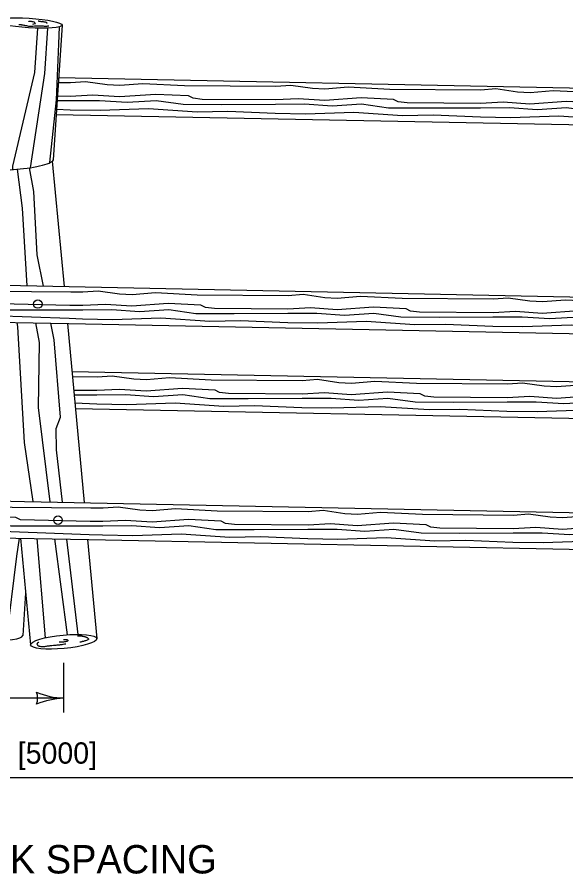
# Model space of a CAD drawing. Extents: x 49991.4 to 50021, y 49987.6 to 50011.4.
# Drawn here: x 50012.107 to 50013.653, y 49994.539 to 49996.952 of the extents above; entities that cross this region are included whole.
import ezdxf

# ---------------------------------------------------------------- set-up
doc = ezdxf.new("R2010")
doc.units = 0
for name, color, linetype in [('Level 1', 7, 'Continuous'), ('Level 2', 7, 'Continuous'), ('Level 3', 7, 'Continuous')]:
    doc.layers.add(name, color=color, linetype=linetype)

msp = doc.modelspace()

# ---------------------------------------------------------------- linework, layer by layer
at = {"layer": 'Level 1'}
for p, q in [((50012.2339, 49996.9293), (50012.2091, 49996.5495)), ((50012.2243, 49996.7817), (50014.3417, 49996.7388)), ((50012.2175, 49996.6777), (50014.3351, 49996.6363)), ((50012.2063, 49996.5461), (50012.2392, 49996.193)), ((50012.0713, 49996.1964), (50014.3767, 49996.1497)), ((50009.7813, 49996.137), (50012.2525, 49996.0886)), ((50012.2489, 49996.0887), (50012.2959, 49995.5846)), ((50012.2525, 49996.0886), (50014.3701, 49996.0471)), ((50012.2615, 49995.9539), (50014.2538, 49995.9136)), ((50012.2712, 49995.8496), (50014.2819, 49995.8102)), ((50009.8457, 49995.6343), (50012.128, 49995.588)), ((50012.128, 49995.588), (50014.4334, 49995.5413)), ((50009.838, 49995.5286), (50012.3092, 49995.4802)), ((50012.1166, 49995.484), (50012.1446, 49995.1842)), ((50012.3056, 49995.4803), (50012.3315, 49995.2015)), ((50012.3092, 49995.4802), (50014.4268, 49995.4387)), ((50012.1309, 49995.3305), (50012.1232, 49995.2101))]:
    msp.add_line(p, q, dxfattribs=at)
for points in [[(50012.095, 49996.5216), (50012.0953, 49996.5317), (50012.157, 49996.7957), (50012.1651, 49996.9206)], [(50012.1449, 49996.5276), (50012.1855, 49996.7929), (50012.1938, 49996.9208)], [(50012.1996, 49996.5421), (50012.2176, 49996.7186), (50012.2244, 49996.8769), (50012.2262, 49996.9246)], [(50012.2577, 49996.7663), (50012.2233, 49996.7666)], [(50012.8356, 49996.7562), (50012.5791, 49996.7583), (50012.4615, 49996.7642), (50012.3962, 49996.7589), (50012.3609, 49996.7608), (50012.3, 49996.7696), (50012.2577, 49996.7663)], [(50013.4136, 49996.7461), (50013.157, 49996.7482), (50013.0395, 49996.7541), (50012.9742, 49996.7488), (50012.9388, 49996.7507), (50012.878, 49996.7595), (50012.8356, 49996.7562)], [(50013.9915, 49996.736), (50013.7349, 49996.7381), (50013.6174, 49996.744), (50013.5521, 49996.7387), (50013.5167, 49996.7406), (50013.4559, 49996.7494), (50013.4135, 49996.7461)], [(50012.2568, 49996.7159), (50012.22, 49996.7157)], [(50012.257, 49996.7286), (50012.2208, 49996.7289)], [(50012.8347, 49996.7058), (50012.6831, 49996.7051), (50012.5753, 49996.7057), (50012.4991, 49996.7162), (50012.4167, 49996.711), (50012.3388, 49996.7162), (50012.2568, 49996.7159)], [(50012.835, 49996.7185), (50012.628, 49996.7201), (50012.6026, 49996.7232), (50012.5899, 49996.7298), (50012.498, 49996.7341), (50012.3957, 49996.7268), (50012.3207, 49996.7319), (50012.257, 49996.7286)], [(50013.4129, 49996.7085), (50013.2059, 49996.7101), (50013.1805, 49996.7131), (50013.1678, 49996.7197), (50013.0759, 49996.724), (50012.9736, 49996.7167), (50012.8986, 49996.7219), (50012.8349, 49996.7185)], [(50012.2564, 49996.6901), (50012.2184, 49996.6917)], [(50012.8343, 49996.68), (50012.7011, 49996.6855), (50012.6146, 49996.6839), (50012.4773, 49996.6932), (50012.3411, 49996.6886), (50012.2564, 49996.6901)], [(50013.4127, 49996.6957), (50013.261, 49996.695), (50013.1533, 49996.6956), (50013.077, 49996.7061), (50012.9946, 49996.7009), (50012.9167, 49996.7061), (50012.8347, 49996.7058)], [(50013.9906, 49996.6857), (50013.8389, 49996.6849), (50013.7312, 49996.6855), (50013.6549, 49996.6961), (50013.5725, 49996.6908), (50013.4946, 49996.6961), (50013.4127, 49996.6957)], [(50013.9908, 49996.6984), (50013.7839, 49996.7), (50013.7584, 49996.703), (50013.7458, 49996.7097), (50013.6539, 49996.7139), (50013.5515, 49996.7066), (50013.4765, 49996.7118), (50013.4129, 49996.7085)], [(50013.4122, 49996.67), (50013.279, 49996.6754), (50013.1925, 49996.6738), (50013.0553, 49996.6832), (50012.9191, 49996.6786), (50012.8343, 49996.68)], [(50013.9901, 49996.6599), (50013.857, 49996.6654), (50013.7705, 49996.6637), (50013.6332, 49996.6731), (50013.497, 49996.6685), (50013.4122, 49996.67)], [(50012.135, 49996.1951), (50012.1222, 49996.4133), (50012.1078, 49996.5231)], [(50012.1816, 49996.1942), (50012.164, 49996.2823), (50012.1538, 49996.4607), (50012.1419, 49996.5271)], [(50012.2583, 49996.1774), (50012.0362, 49996.1792), (50011.9186, 49996.1851), (50011.8534, 49996.1798), (50011.818, 49996.1817), (50011.7572, 49996.1905), (50011.7148, 49996.1872)], [(50012.2927, 49996.1771), (50012.2583, 49996.1774)], [(50012.8707, 49996.1671), (50012.6141, 49996.1691), (50012.4966, 49996.175), (50012.4313, 49996.1697), (50012.3959, 49996.1716), (50012.3351, 49996.1804), (50012.2927, 49996.1771)], [(50013.4486, 49996.157), (50013.192, 49996.1591), (50013.0745, 49996.165), (50013.0092, 49996.1597), (50012.9738, 49996.1616), (50012.913, 49996.1704), (50012.8706, 49996.1671)], [(50014.0265, 49996.1469), (50013.7699, 49996.149), (50013.6524, 49996.1549), (50013.5871, 49996.1496), (50013.5517, 49996.1515), (50013.4909, 49996.1603), (50013.4485, 49996.157)], [(50012.2559, 49996.1398), (50012.0597, 49996.1441), (50012.047, 49996.1508), (50011.9551, 49996.155), (50011.8528, 49996.1477), (50011.7778, 49996.1529), (50011.7141, 49996.1496)], [(50012.2921, 49996.1395), (50012.2559, 49996.1398)], [(50012.87, 49996.1294), (50012.663, 49996.131), (50012.6376, 49996.1341), (50012.625, 49996.1407), (50012.533, 49996.1449), (50012.4307, 49996.1377), (50012.3557, 49996.1428), (50012.292, 49996.1395)], [(50012.2534, 49996.1025), (50011.9344, 49996.1142), (50011.7982, 49996.1096), (50011.7135, 49996.1111)], [(50012.2918, 49996.1268), (50012.0668, 49996.1264)], [(50012.8698, 49996.1167), (50012.7181, 49996.1159), (50012.6104, 49996.1165), (50012.5341, 49996.1271), (50012.4517, 49996.1219), (50012.3738, 49996.1271), (50012.2918, 49996.1268)], [(50013.4477, 49996.1066), (50013.296, 49996.1059), (50013.1883, 49996.1065), (50013.112, 49996.117), (50013.0296, 49996.1118), (50012.9517, 49996.117), (50012.8698, 49996.1167)], [(50013.4479, 49996.1193), (50013.241, 49996.1209), (50013.2155, 49996.124), (50013.2029, 49996.1306), (50013.111, 49996.1349), (50013.0086, 49996.1276), (50012.9336, 49996.1327), (50012.87, 49996.1294)], [(50014.0258, 49996.1093), (50013.8189, 49996.1109), (50013.7934, 49996.1139), (50013.7808, 49996.1206), (50013.6889, 49996.1248), (50013.5866, 49996.1175), (50013.5115, 49996.1227), (50013.4479, 49996.1193)], [(50012.1522, 49995.5875), (50012.128, 49995.7534), (50012.1093, 49996.0799), (50012.1074, 49996.0915)], [(50012.1999, 49995.5865), (50012.1677, 49995.8525), (50012.1699, 49996.0355), (50012.1594, 49996.0904)], [(50012.235, 49995.5858), (50012.2176, 49995.7327), (50012.2171, 49995.7936), (50012.229, 49995.8253), (50012.2116, 49996.0433), (50012.2024, 49996.0896)], [(50012.2914, 49996.101), (50012.2534, 49996.1025)], [(50012.8693, 49996.0909), (50012.7361, 49996.0964), (50012.6496, 49996.0947), (50012.5124, 49996.1041), (50012.3762, 49996.0995), (50012.2914, 49996.101)], [(50013.4472, 49996.0808), (50013.3141, 49996.0863), (50013.2276, 49996.0847), (50013.0903, 49996.0941), (50012.9541, 49996.0894), (50012.8693, 49996.0909)], [(50014.0256, 49996.0966), (50013.8739, 49996.0958), (50013.7662, 49996.0964), (50013.6899, 49996.107), (50013.6076, 49996.1017), (50013.5297, 49996.107), (50013.4477, 49996.1066)], [(50014.0252, 49996.0708), (50013.892, 49996.0762), (50013.8055, 49996.0746), (50013.6682, 49996.084), (50013.532, 49996.0794), (50013.4472, 49996.0808)], [(50012.3326, 49995.9377), (50012.2629, 49995.9383)], [(50012.9106, 49995.9277), (50012.654, 49995.9297), (50012.5365, 49995.9356), (50012.4712, 49995.9303), (50012.4358, 49995.9322), (50012.375, 49995.941), (50012.3326, 49995.9377)], [(50013.4885, 49995.9176), (50013.2319, 49995.9197), (50013.1144, 49995.9256), (50013.0491, 49995.9203), (50013.0137, 49995.9222), (50012.9529, 49995.931), (50012.9105, 49995.9277)], [(50014.0664, 49995.9075), (50013.8098, 49995.9096), (50013.6923, 49995.9155), (50013.627, 49995.9102), (50013.5916, 49995.9121), (50013.5308, 49995.9209), (50013.4884, 49995.9176)], [(50012.332, 49995.9001), (50012.2665, 49995.9006)], [(50012.9099, 49995.89), (50012.703, 49995.8916), (50012.6775, 49995.8946), (50012.6649, 49995.9013), (50012.5729, 49995.9055), (50012.4706, 49995.8983), (50012.3956, 49995.9034), (50012.3319, 49995.9001)], [(50013.4878, 49995.8799), (50013.2809, 49995.8815), (50013.2554, 49995.8846), (50013.2428, 49995.8912), (50013.1509, 49995.8955), (50013.0485, 49995.8882), (50012.9735, 49995.8933), (50012.9099, 49995.89)], [(50012.3317, 49995.8874), (50012.2677, 49995.887)], [(50012.9097, 49995.8773), (50012.758, 49995.8765), (50012.6503, 49995.8771), (50012.574, 49995.8877), (50012.4916, 49995.8825), (50012.4137, 49995.8877), (50012.3317, 49995.8874)], [(50013.4876, 49995.8672), (50013.3359, 49995.8665), (50013.2282, 49995.8671), (50013.1519, 49995.8776), (50013.0695, 49995.8724), (50012.9916, 49995.8776), (50012.9097, 49995.8773)], [(50014.0657, 49995.8698), (50013.8588, 49995.8715), (50013.8333, 49995.8745), (50013.8207, 49995.8811), (50013.7288, 49995.8854), (50013.6265, 49995.8781), (50013.5514, 49995.8832), (50013.4878, 49995.8799)], [(50012.3313, 49995.8616), (50012.2699, 49995.8641)], [(50012.9092, 49995.8515), (50012.776, 49995.857), (50012.6896, 49995.8553), (50012.5523, 49995.8647), (50012.4161, 49995.8601), (50012.3313, 49995.8616)], [(50013.4871, 49995.8414), (50013.354, 49995.8469), (50013.2675, 49995.8453), (50013.1302, 49995.8546), (50012.994, 49995.85), (50012.9092, 49995.8515)], [(50014.0655, 49995.8571), (50013.9138, 49995.8564), (50013.8061, 49995.857), (50013.7298, 49995.8675), (50013.6475, 49995.8623), (50013.5696, 49995.8675), (50013.4876, 49995.8672)], [(50014.0651, 49995.8314), (50013.9319, 49995.8368), (50013.8454, 49995.8352), (50013.7081, 49995.8446), (50013.5719, 49995.84), (50013.4871, 49995.8414)], [(50012.315, 49995.5691), (50012.0929, 49995.5708), (50011.9753, 49995.5767), (50011.91, 49995.5714), (50011.8746, 49995.5733), (50011.8138, 49995.5821), (50011.7715, 49995.5788)], [(50012.3494, 49995.5688), (50012.315, 49995.5691)], [(50012.9273, 49995.5587), (50012.6708, 49995.5608), (50012.5532, 49995.5666), (50012.488, 49995.5613), (50012.4526, 49995.5633), (50012.3918, 49995.572), (50012.3494, 49995.5688)], [(50013.5053, 49995.5486), (50013.2487, 49995.5507), (50013.1312, 49995.5566), (50013.0659, 49995.5513), (50013.0305, 49995.5532), (50012.9697, 49995.562), (50012.9273, 49995.5587)], [(50012.3126, 49995.5314), (50012.1164, 49995.5357), (50012.1037, 49995.5424), (50012.0118, 49995.5466), (50011.9095, 49995.5394), (50011.8345, 49995.5445), (50011.7708, 49995.5412)], [(50012.9267, 49995.521), (50012.7197, 49995.5226), (50012.6943, 49995.5257), (50012.6816, 49995.5323), (50012.5897, 49995.5366), (50012.4874, 49995.5293), (50012.4124, 49995.5344), (50012.3487, 49995.5311)], [(50014.0832, 49995.5385), (50013.8266, 49995.5406), (50013.7091, 49995.5465), (50013.6438, 49995.5412), (50013.6084, 49995.5431), (50013.5476, 49995.5519), (50013.5052, 49995.5486)], [(50012.1235, 49995.518), (50012.0891, 49995.5182), (50012.0129, 49995.5288), (50011.9305, 49995.5236), (50011.8526, 49995.5288), (50011.7706, 49995.5285)], [(50012.3485, 49995.5184), (50012.1235, 49995.518)], [(50012.3488, 49995.5311), (50012.3126, 49995.5314)], [(50012.9265, 49995.5083), (50012.7748, 49995.5076), (50012.6671, 49995.5081), (50012.5908, 49995.5187), (50012.5084, 49995.5135), (50012.4305, 49995.5187), (50012.3485, 49995.5184)], [(50013.5046, 49995.5109), (50013.2977, 49995.5126), (50013.2722, 49995.5156), (50013.2596, 49995.5222), (50013.1677, 49995.5265), (50013.0653, 49995.5192), (50012.9903, 49995.5243), (50012.9267, 49995.521)], [(50014.0825, 49995.5009), (50013.8756, 49995.5025), (50013.8501, 49995.5055), (50013.8375, 49995.5122), (50013.7456, 49995.5164), (50013.6433, 49995.5091), (50013.5682, 49995.5143), (50013.5046, 49995.5109)], [(50012.3101, 49995.4942), (50011.9911, 49995.5058), (50011.8549, 49995.5012), (50011.7702, 49995.5027)], [(50012.3481, 49995.4926), (50012.3101, 49995.4942)], [(50012.926, 49995.4825), (50012.7928, 49995.488), (50012.7063, 49995.4863), (50012.5691, 49995.4957), (50012.4329, 49995.4911), (50012.3481, 49995.4926)], [(50013.5039, 49995.4725), (50013.3708, 49995.4779), (50013.2843, 49995.4763), (50013.147, 49995.4857), (50013.0108, 49995.481), (50012.926, 49995.4825)], [(50013.5044, 49995.4982), (50013.3527, 49995.4975), (50013.245, 49995.4981), (50013.1687, 49995.5086), (50013.0863, 49995.5034), (50013.0084, 49995.5086), (50012.9265, 49995.5083)], [(50014.0823, 49995.4882), (50013.9306, 49995.4874), (50013.8229, 49995.488), (50013.7466, 49995.4986), (50013.6643, 49995.4933), (50013.5864, 49995.4986), (50013.5044, 49995.4982)], [(50012.0768, 49995.1975), (50012.1066, 49995.4338), (50012.1136, 49995.484)], [(50012.187, 49995.2038), (50012.1633, 49995.483)], [(50012.249, 49995.2125), (50012.2137, 49995.4821)], [(50012.279, 49995.2135), (50012.2473, 49995.4814)], [(50014.0818, 49995.4624), (50013.9487, 49995.4678), (50013.8622, 49995.4662), (50013.7249, 49995.4756), (50013.5887, 49995.471), (50013.5039, 49995.4725)]]:
    msp.add_lwpolyline(points, dxfattribs=at)
for centre in [(50012.1657, 49996.1437), (50012.2223, 49995.5353)]:
    msp.add_circle(centre, 0.012, dxfattribs=at)
for centre, major_axis, ratio in [((50012.1401, 49996.9351), (0.0937, -0.0058), 0.143064), ((50012.2382, 49995.1926), (0.0932, 0.0089), 0.201992)]:
    msp.add_ellipse(centre, major_axis=major_axis, ratio=ratio, dxfattribs=at)
for centre, major_axis, ratio, start_param, end_param in [((50012.1168, 49996.5431), (0.0932, 0.0089), 0.201992, 4.679863, 6.355951), ((50012.1158, 49996.505), (0.0934, 0.0089), 0.201542, 1.555621, 3.157543), ((50012.0294, 49995.2163), (-0.0937, 0.0061), 0.194104, 0.000064, 3.132664)]:
    msp.add_ellipse(centre, major_axis=major_axis, ratio=ratio, start_param=start_param, end_param=end_param, dxfattribs=at)
for points in [[(50012.1518, 49996.9318), (50012.1573, 49996.9336), (50012.1587, 49996.9338), (50012.1561, 49996.9367), (50012.1552, 49996.9373), (50012.1498, 49996.9388), (50012.1446, 49996.9394), (50012.1403, 49996.9394), (50012.1398, 49996.9399)], [(50012.1661, 49996.9412), (50012.1685, 49996.9405), (50012.1718, 49996.9402), (50012.1762, 49996.9394), (50012.1802, 49996.9393), (50012.1854, 49996.9381), (50012.1876, 49996.9378), (50012.1901, 49996.9363), (50012.1909, 49996.935), (50012.1914, 49996.9338), (50012.1914, 49996.9336)], [(50012.1117, 49996.9311), (50012.117, 49996.9311), (50012.1199, 49996.9301), (50012.1258, 49996.9293), (50012.1306, 49996.9282), (50012.1363, 49996.9272), (50012.1429, 49996.9262), (50012.1465, 49996.9262), (50012.156, 49996.9268), (50012.1561, 49996.9268), (50012.1622, 49996.9272), (50012.1696, 49996.9268), (50012.1802, 49996.9268), (50012.1862, 49996.9258), (50012.1914, 49996.9262), (50012.1962, 49996.9275)], [(50012.2375, 49995.199), (50012.2407, 49995.1994), (50012.2449, 49995.199), (50012.247, 49995.1987), (50012.2498, 49995.1972), (50012.25, 49995.1955), (50012.2474, 49995.1937), (50012.2431, 49995.1926), (50012.2382, 49995.1919), (50012.2347, 49995.1914), (50012.2292, 49995.1913), (50012.2265, 49995.1913), (50012.2256, 49995.1913)], [(50012.277, 49995.2096), (50012.2816, 49995.2096), (50012.2861, 49995.2096), (50012.2893, 49995.2089), (50012.2922, 49995.2081), (50012.297, 49995.2075), (50012.2993, 49995.2066), (50012.303, 49995.2054), (50012.3045, 49995.2046), (50012.3057, 49995.2034), (50012.3072, 49995.2019), (50012.3081, 49995.1997), (50012.3075, 49995.1987), (50012.3049, 49995.1972), (50012.2993, 49995.1955), (50012.2975, 49995.1949), (50012.2908, 49995.1929), (50012.2884, 49995.1924), (50012.2853, 49995.1913), (50012.2838, 49995.1913)], [(50012.1686, 49995.1913), (50012.1664, 49995.1903), (50012.1638, 49995.1882), (50012.163, 49995.186), (50012.1643, 49995.1838), (50012.1656, 49995.1818), (50012.168, 49995.1807), (50012.1712, 49995.1799), (50012.1771, 49995.1797), (50012.1853, 49995.1797), (50012.1901, 49995.1805), (50012.1956, 49995.181), (50012.205, 49995.1825), (50012.2134, 49995.1831), (50012.2201, 49995.1836), (50012.2274, 49995.1842), (50012.2364, 49995.1857), (50012.2445, 49995.187)]]:
    msp.add_spline(points, degree=3, dxfattribs=at)
at = {"layer": 'Level 3'}
for p, q in [((50012.2382, 49995.1336), (50012.2382, 49994.9936)), ((50012.2382, 49995.0336), (50009.9521, 49995.0336)), ((50014.5466, 49994.8093), (50009.9521, 49994.8093))]:
    msp.add_line(p, q, dxfattribs=at)
for centre, radius, start, end in [((50012.2474, 49995.2558), 0.2223, 247.456, 267.6395), ((50012.11, 49995.0336), 0.0548, 342.1388, 17.8612), ((50012.2497, 49994.8009), 0.233, 92.8273, 112.0772)]:
    msp.add_arc(centre, radius, start, end, dxfattribs=at)

# ---------------------------------------------------------------- texts
at = {"layer": 'Level 2'}
msp.add_text('16\'-6" [5000]', height=0.06, rotation=0, dxfattribs=at).set_placement((50011.8823, 49994.8493))
msp.add_text('LINE JACK SPACING', height=0.08, dxfattribs=at).set_placement((50011.6172, 49994.5401))

doc.saveas('drawing.dxf')
